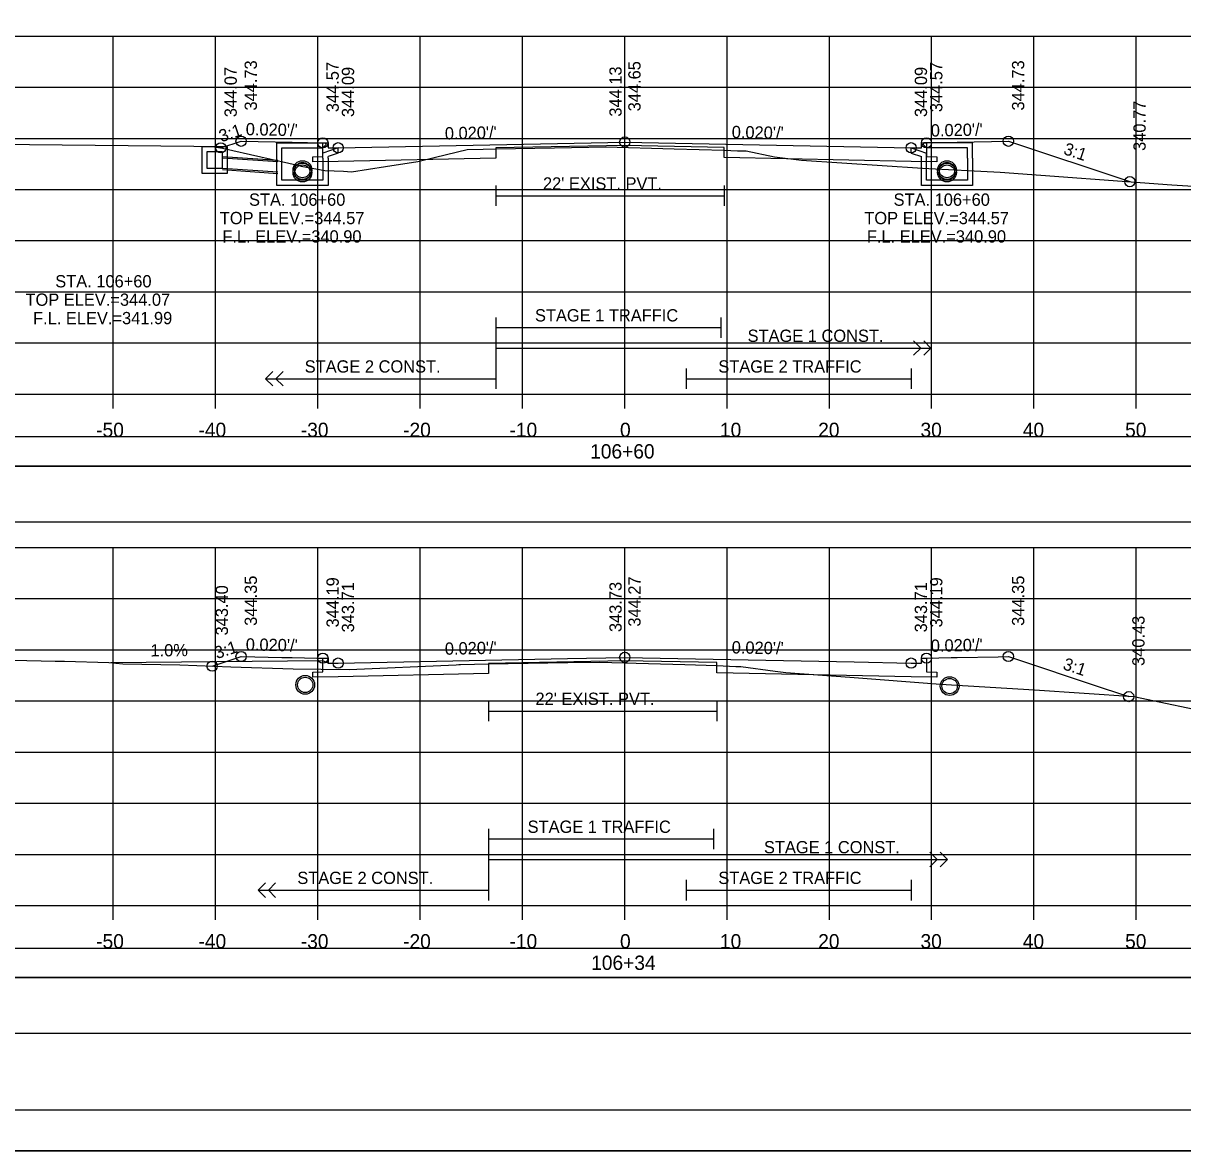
# Model space of a CAD drawing. Extents: x 1368122 to 1710785, y 373130 to 557566.
# Drawn here: x 1368630.1 to 1368743.4, y 374410.4 to 374520.6 of the extents above; entities that cross this region are included whole.
import ezdxf

# ---------------------------------------------------------------- set-up
doc = ezdxf.new("R2010")
doc.units = 0
for name, color, linetype in [('R_Alt Surface', 7, 'Continuous'), ('R_Axis', 7, 'Continuous'), ('R_Axis Annot', 7, 'Continuous'), ('R_Border', 7, 'Continuous'), ('R_Drive', 7, 'Continuous'), ('R_Exist Surface', 7, 'Continuous'), ('R_Fin Surface', 7, 'Continuous'), ('R_Grid', 7, 'Continuous'), ('R_No Plot', 7, 'Continuous'), ('R_Striping', 7, 'Continuous'), ('R_Water', 7, 'Continuous'), ('R_Water Annot', 7, 'Continuous'), ('R_Xsect Elev', 7, 'Continuous'), ('R_Xsect Slope', 7, 'Continuous')]:
    doc.layers.add(name, color=color, linetype=linetype)

msp = doc.modelspace()

# ---------------------------------------------------------------- linework, layer by layer
at = {"layer": 'R_Alt Surface'}
for points in [[(1368718.38, 374508.9), (1368718.38, 374507.56), (1368719.38, 374507.54), (1368719.38, 374507.04), (1368716.88, 374507.09), (1368698.6, 374507.46), (1368698.6, 374508.46), (1368688.88, 374508.65), (1368676.28, 374508.4), (1368676.28, 374507.4), (1368660.88, 374507.09), (1368658.38, 374507.04), (1368658.38, 374507.54), (1368659.38, 374507.56), (1368659.38, 374508.9)], [(1368676.28, 374504.73), (1368676.28, 374502.73)], [(1368698.6, 374504.73), (1368698.6, 374502.73)], [(1368676.28, 374503.73), (1368698.6, 374503.73)], [(1368718.38, 374458.52), (1368718.38, 374457.18), (1368719.38, 374457.16), (1368719.38, 374456.66), (1368716.88, 374456.71), (1368697.87, 374457.09), (1368697.87, 374458.09), (1368688.88, 374458.27), (1368675.55, 374458.01), (1368675.55, 374457.01), (1368660.88, 374456.71), (1368658.38, 374456.66), (1368658.38, 374457.16), (1368659.38, 374457.18), (1368659.38, 374458.52)], [(1368675.55, 374454.35), (1368675.55, 374452.35)], [(1368697.87, 374454.35), (1368697.87, 374452.35)], [(1368675.55, 374453.35), (1368697.87, 374453.35)]]:
    msp.add_lwpolyline(points, dxfattribs=at)
for points in [[(1368539.73, 374477.33), (1368838.03, 374477.33), (1368838.03, 374480.15), (1368539.73, 374480.15)], [(1368539.73, 374471.86), (1368838.03, 374471.86), (1368838.03, 374477.27), (1368539.73, 374477.27)], [(1368539.73, 374427.33), (1368838.03, 374427.33), (1368838.03, 374430.15), (1368539.73, 374430.15)], [(1368539.73, 374421.86), (1368838.03, 374421.86), (1368838.03, 374427.27), (1368539.73, 374427.27)]]:
    msp.add_lwpolyline(points, close=True, dxfattribs=at)
at = {"layer": 'R_Axis'}
for p, q in [((1368538.88, 374484.34), (1368838.88, 374484.34)), ((1368638.88, 374482.94), (1368638.88, 374484.34)), ((1368648.88, 374482.94), (1368648.88, 374484.34)), ((1368658.88, 374482.94), (1368658.88, 374484.34)), ((1368668.88, 374482.94), (1368668.88, 374484.34)), ((1368678.88, 374482.94), (1368678.88, 374484.34)), ((1368688.88, 374482.94), (1368688.88, 374484.34)), ((1368698.88, 374482.94), (1368698.88, 374484.34)), ((1368708.88, 374482.94), (1368708.88, 374484.34)), ((1368718.88, 374482.94), (1368718.88, 374484.34)), ((1368728.88, 374482.94), (1368728.88, 374484.34)), ((1368738.88, 374482.94), (1368738.88, 374484.34)), ((1368538.88, 374434.34), (1368838.88, 374434.34)), ((1368638.88, 374432.94), (1368638.88, 374434.34)), ((1368648.88, 374432.94), (1368648.88, 374434.34)), ((1368658.88, 374432.94), (1368658.88, 374434.34)), ((1368668.88, 374432.94), (1368668.88, 374434.34)), ((1368678.88, 374432.94), (1368678.88, 374434.34)), ((1368688.88, 374432.94), (1368688.88, 374434.34)), ((1368698.88, 374432.94), (1368698.88, 374434.34)), ((1368708.88, 374432.94), (1368708.88, 374434.34)), ((1368718.88, 374432.94), (1368718.88, 374434.34)), ((1368728.88, 374432.94), (1368728.88, 374434.34)), ((1368738.88, 374432.94), (1368738.88, 374434.34))]:
    msp.add_line(p, q, dxfattribs=at)
at = {"layer": 'R_Border'}
msp.add_line((1368847.06, 374414.34), (1368530.88, 374414.34), dxfattribs=at)
at = {"layer": 'R_Drive'}
for p, q in [((1368659.38, 374458.27), (1368638.66, 374458.07)), ((1368659.88, 374458.02), (1368659.38, 374458.27))]:
    msp.add_line(p, q, dxfattribs=at)
at = {"layer": 'R_Exist Surface'}
for points in [[(1368617.79, 374508.86), (1368646.78, 374508.58), (1368648.11, 374508.54), (1368648.37, 374508.54), (1368648.8, 374508.52), (1368649.57, 374508.38), (1368657.07, 374506.69), (1368657.25, 374506.62), (1368659.56, 374506.2), (1368661.38, 374506.13), (1368662.17, 374506.08), (1368665.49, 374506.58), (1368668.66, 374507.07), (1368670.38, 374507.51), (1368673.48, 374508.24), (1368675.03, 374508.28), (1368676.28, 374508.31), (1368682.02, 374508.42), (1368687.02, 374508.52), (1368693.7, 374508.31), (1368698.6, 374508.17), (1368699.92, 374508.13), (1368700.75, 374508.11), (1368703.53, 374507.52), (1368706.17, 374507.2), (1368717.99, 374506.41), (1368725.57, 374506.03), (1368742.37, 374504.81), (1368748.06, 374504.43)], [(1368622.12, 374458.49), (1368633.2, 374458.24), (1368633.75, 374458.22), (1368634.13, 374458.22), (1368638.46, 374458.08), (1368639.84, 374457.97), (1368645.4, 374457.87), (1368650.39, 374457.67), (1368656.47, 374457.47), (1368661.95, 374457.42), (1368672.4, 374457.88), (1368672.66, 374457.89), (1368672.78, 374457.89), (1368672.79, 374457.89), (1368672.82, 374457.89), (1368675.55, 374457.96), (1368683.31, 374458.08), (1368686.44, 374458.14), (1368694.75, 374457.89), (1368697.87, 374457.79), (1368699.75, 374457.72), (1368700.23, 374457.7), (1368703.6, 374457.26), (1368704.62, 374457.12), (1368710.89, 374456.67), (1368719.74, 374455.99), (1368728.94, 374455.43), (1368738.65, 374454.78), (1368747.03, 374453)]]:
    msp.add_lwpolyline(points, dxfattribs=at)
for centre in [(1368657.65, 374455.91), (1368720.64, 374455.79)]:
    msp.add_circle(centre, 0.917, dxfattribs=at)
at = {"layer": 'R_Fin Surface'}
for points in [[(1368649.41, 374508.41), (1368651.38, 374509.06), (1368656.38, 374508.96), (1368659.38, 374508.9), (1368659.88, 374508.9), (1368659.88, 374508.4), (1368660.88, 374508.42), (1368688.88, 374508.98), (1368716.88, 374508.42), (1368717.88, 374508.4), (1368717.88, 374508.9), (1368718.38, 374508.9), (1368721.38, 374508.96), (1368726.38, 374509.06), (1368738.25, 374505.11)], [(1368648.55, 374457.74), (1368650.82, 374458.5), (1368651.38, 374458.68), (1368655.38, 374458.6), (1368656.38, 374458.58), (1368658.78, 374458.53), (1368659.38, 374458.52), (1368659.48, 374458.52), (1368659.88, 374458.52), (1368659.88, 374458.42), (1368659.88, 374458.02), (1368660.68, 374458.04), (1368660.88, 374458.04), (1368683.3, 374458.49), (1368688.88, 374458.6), (1368711.3, 374458.15), (1368716.88, 374458.04), (1368717.08, 374458.04), (1368717.88, 374458.02), (1368717.88, 374458.12), (1368717.88, 374458.52), (1368718.28, 374458.52), (1368718.38, 374458.52), (1368720.78, 374458.57), (1368721.38, 374458.58), (1368725.38, 374458.66), (1368726.38, 374458.68), (1368735.66, 374455.59), (1368738.14, 374454.76)]]:
    msp.add_lwpolyline(points, dxfattribs=at)
at = {"layer": 'R_Grid'}
for p, q in [((1368538.88, 374519.34), (1368838.88, 374519.34)), ((1368638.88, 374484.34), (1368638.88, 374519.34)), ((1368648.88, 374484.34), (1368648.88, 374519.34)), ((1368658.88, 374484.34), (1368658.88, 374519.34)), ((1368668.88, 374484.34), (1368668.88, 374519.34)), ((1368678.88, 374484.34), (1368678.88, 374519.34)), ((1368688.88, 374484.34), (1368688.88, 374519.34)), ((1368698.88, 374484.34), (1368698.88, 374519.34)), ((1368708.88, 374484.34), (1368708.88, 374519.34)), ((1368718.88, 374484.34), (1368718.88, 374519.34)), ((1368728.88, 374484.34), (1368728.88, 374519.34)), ((1368738.88, 374484.34), (1368738.88, 374519.34)), ((1368538.88, 374514.34), (1368838.88, 374514.34)), ((1368538.88, 374509.34), (1368838.88, 374509.34)), ((1368538.88, 374504.34), (1368838.88, 374504.34)), ((1368538.88, 374499.34), (1368838.88, 374499.34)), ((1368538.88, 374494.34), (1368838.88, 374494.34)), ((1368538.88, 374489.34), (1368838.88, 374489.34)), ((1368538.88, 374484.34), (1368838.88, 374484.34)), ((1368538.88, 374469.34), (1368838.88, 374469.34)), ((1368638.88, 374434.34), (1368638.88, 374469.34)), ((1368648.88, 374434.34), (1368648.88, 374469.34)), ((1368658.88, 374434.34), (1368658.88, 374469.34)), ((1368668.88, 374434.34), (1368668.88, 374469.34)), ((1368678.88, 374434.34), (1368678.88, 374469.34)), ((1368688.88, 374434.34), (1368688.88, 374469.34)), ((1368698.88, 374434.34), (1368698.88, 374469.34)), ((1368708.88, 374434.34), (1368708.88, 374469.34)), ((1368718.88, 374434.34), (1368718.88, 374469.34)), ((1368728.88, 374434.34), (1368728.88, 374469.34)), ((1368738.88, 374434.34), (1368738.88, 374469.34)), ((1368538.88, 374464.34), (1368838.88, 374464.34)), ((1368538.88, 374459.34), (1368838.88, 374459.34)), ((1368538.88, 374454.34), (1368838.88, 374454.34)), ((1368538.88, 374449.34), (1368838.88, 374449.34)), ((1368538.88, 374444.34), (1368838.88, 374444.34)), ((1368538.88, 374439.34), (1368838.88, 374439.34)), ((1368538.88, 374434.34), (1368838.88, 374434.34))]:
    msp.add_line(p, q, dxfattribs=at)
at = {"layer": 'R_No Plot'}
for p, q in [((1368649.55, 374507.58), (1368654.99, 374507.22)), ((1368649.55, 374506.28), (1368654.99, 374505.92)), ((1368518.48, 374410.36), (1368851.81, 374410.36))]:
    msp.add_line(p, q, dxfattribs=at)
for points in [[(1368518.47, 374623.69), (1368851.81, 374623.69), (1368851.81, 374410.35), (1368518.47, 374410.35)], [(1368764.8, 374619.8), (1368784.42, 374619.8), (1368784.42, 374609.92), (1368800.53, 374609.92), (1368823.73, 374609.92), (1368823.85, 374581.76), (1368847.06, 374581.76), (1368847.06, 374414.34), (1368530.88, 374414.34), (1368530.88, 374619.8)]]:
    msp.add_lwpolyline(points, close=True, dxfattribs=at)
for centre, radius in [((1368651.38, 374509.06), 0.5), ((1368688.88, 374508.98), 0.5), ((1368726.38, 374509.06), 0.5), ((1368649.41, 374508.41), 0.5), ((1368659.38, 374508.9), 0.5), ((1368660.88, 374508.42), 0.5), ((1368716.88, 374508.42), 0.5), ((1368718.38, 374508.9), 0.5), ((1368657.38, 374506.24), 0.917), ((1368720.38, 374506.24), 0.917), ((1368657.38, 374505.99), 0.917), ((1368720.38, 374505.99), 0.917), ((1368738.25, 374505.11), 0.5), ((1368651.38, 374458.68), 0.5), ((1368659.38, 374458.52), 0.5), ((1368660.88, 374458.04), 0.5), ((1368688.88, 374458.6), 0.5), ((1368716.88, 374458.04), 0.5), ((1368718.38, 374458.52), 0.5), ((1368726.38, 374458.68), 0.5), ((1368648.55, 374457.74), 0.5), ((1368738.14, 374454.76), 0.5)]:
    msp.add_circle(centre, radius, dxfattribs=at)
at = {"layer": 'R_Striping'}
for p, q in [((1368717.81, 374488.84), (1368717.11, 374489.54)), ((1368718.81, 374488.84), (1368718.11, 374489.54)), ((1368717.11, 374488.13), (1368717.81, 374488.84)), ((1368718.11, 374488.13), (1368718.81, 374488.84)), ((1368653.78, 374485.84), (1368654.49, 374486.54)), ((1368653.78, 374485.84), (1368676.28, 374485.84)), ((1368654.49, 374485.13), (1368653.78, 374485.84)), ((1368654.78, 374485.84), (1368655.49, 374486.54)), ((1368655.49, 374485.13), (1368654.78, 374485.84)), ((1368719.42, 374438.84), (1368718.71, 374439.54)), ((1368720.42, 374438.84), (1368719.71, 374439.54)), ((1368718.71, 374438.13), (1368719.42, 374438.84)), ((1368719.71, 374438.13), (1368720.42, 374438.84)), ((1368653.05, 374435.84), (1368653.76, 374436.54)), ((1368653.05, 374435.84), (1368675.55, 374435.84)), ((1368653.76, 374435.13), (1368653.05, 374435.84)), ((1368654.05, 374435.84), (1368654.76, 374436.54)), ((1368654.76, 374435.13), (1368654.05, 374435.84))]:
    msp.add_line(p, q, dxfattribs=at)
for points in [[(1368676.28, 374491.84), (1368676.28, 374484.84)], [(1368698.28, 374491.84), (1368698.28, 374489.84)], [(1368676.28, 374490.84), (1368698.28, 374490.84)], [(1368676.28, 374488.84), (1368718.81, 374488.84)], [(1368694.88, 374486.84), (1368694.88, 374484.84)], [(1368716.88, 374486.84), (1368716.88, 374484.84)], [(1368694.88, 374485.84), (1368716.88, 374485.84)], [(1368675.55, 374441.84), (1368675.55, 374434.84)], [(1368697.55, 374441.84), (1368697.55, 374439.84)], [(1368675.55, 374440.84), (1368697.55, 374440.84)], [(1368675.55, 374438.84), (1368720.42, 374438.84)], [(1368694.88, 374436.84), (1368694.88, 374434.84)], [(1368694.88, 374435.84), (1368716.88, 374435.84)], [(1368716.88, 374436.84), (1368716.88, 374434.84)]]:
    msp.add_lwpolyline(points, dxfattribs=at)
at = {"layer": 'R_Water'}
for p, q in [((1368654.88, 374508.9), (1368659.63, 374508.9)), ((1368654.88, 374507.4), (1368654.88, 374508.9)), ((1368655.38, 374507.4), (1368655.38, 374508.4)), ((1368655.38, 374508.4), (1368659.38, 374508.4)), ((1368659.71, 374508.74), (1368659.38, 374508.4)), ((1368660.88, 374508.42), (1368659.38, 374507.9)), ((1368659.71, 374508.74), (1368659.63, 374508.9)), ((1368716.88, 374508.42), (1368718.38, 374507.9)), ((1368718.05, 374508.74), (1368718.13, 374508.9)), ((1368718.05, 374508.74), (1368718.38, 374508.4)), ((1368722.88, 374508.9), (1368718.13, 374508.9)), ((1368722.38, 374508.4), (1368718.38, 374508.4)), ((1368722.38, 374507.4), (1368722.38, 374508.4)), ((1368722.88, 374507.4), (1368722.88, 374508.9)), ((1368649.55, 374507.43), (1368654.99, 374507.07)), ((1368659.38, 374507.4), (1368659.38, 374507.9)), ((1368660.88, 374507.89), (1368659.88, 374507.55)), ((1368659.88, 374507.4), (1368659.88, 374507.55)), ((1368716.88, 374507.89), (1368717.88, 374507.55)), ((1368717.88, 374507.4), (1368717.88, 374507.55)), ((1368718.38, 374507.4), (1368718.38, 374507.9)), ((1368649.55, 374506.43), (1368654.99, 374506.07))]:
    msp.add_line(p, q, dxfattribs=at)
for points in [[(1368648.8, 374508.52), (1368647.55, 374508.52), (1368647.55, 374505.93), (1368648.8, 374505.93), (1368650.05, 374505.93), (1368650.05, 374508.52)], [(1368648.8, 374508.02), (1368648.05, 374508.02), (1368648.05, 374506.43), (1368648.8, 374506.43), (1368649.55, 374506.43), (1368649.55, 374508.02)]]:
    msp.add_lwpolyline(points, close=True, dxfattribs=at)
for points in [[(1368660.88, 374507.89), (1368660.88, 374508.42)], [(1368716.88, 374507.89), (1368716.88, 374508.42)], [(1368659.88, 374507.4), (1368659.88, 374504.74), (1368657.38, 374504.74), (1368654.88, 374504.74), (1368654.88, 374507.4)], [(1368659.38, 374507.4), (1368659.38, 374505.24), (1368657.38, 374505.24), (1368655.38, 374505.24), (1368655.38, 374507.4)], [(1368722.88, 374507.4), (1368722.88, 374504.74), (1368720.38, 374504.74), (1368717.88, 374504.74), (1368717.88, 374507.4)], [(1368722.38, 374507.4), (1368722.38, 374505.24), (1368720.38, 374505.24), (1368718.38, 374505.24), (1368718.38, 374507.4)]]:
    msp.add_lwpolyline(points, dxfattribs=at)
for centre in [(1368657.38, 374506.24), (1368657.38, 374505.99), (1368720.38, 374506.24), (1368720.38, 374505.99), (1368657.65, 374455.91), (1368720.64, 374455.79)]:
    msp.add_circle(centre, 0.75, dxfattribs=at)
at = {"layer": 'R_Xsect Elev'}
for p, q in [((1368688.88, 374508.46), (1368688.88, 374518.46)), ((1368688.88, 374458.07), (1368688.88, 374468.07))]:
    msp.add_line(p, q, dxfattribs=at)

# ---------------------------------------------------------------- texts
at = {"layer": 'R_Axis Annot'}
for s, p in [('-50', (1368637.22, 374480.14)), ('-40', (1368647.22, 374480.14)), ('-30', (1368657.22, 374480.14)), ('-20', (1368667.22, 374480.14)), ('-10', (1368677.62, 374480.14)), ('0', (1368688.42, 374480.14)), ('10', (1368698.19, 374480.14)), ('20', (1368707.79, 374480.14)), ('30', (1368717.79, 374480.14)), ('40', (1368727.79, 374480.14)), ('50', (1368737.79, 374480.14)), ('106+60', (1368685.5, 374478.04)), ('-50', (1368637.22, 374430.14)), ('-40', (1368647.22, 374430.14)), ('-30', (1368657.22, 374430.14)), ('-20', (1368667.22, 374430.14)), ('-10', (1368677.62, 374430.14)), ('0', (1368688.42, 374430.14)), ('10', (1368698.19, 374430.14)), ('20', (1368707.79, 374430.14)), ('30', (1368717.79, 374430.14)), ('40', (1368727.79, 374430.14)), ('50', (1368737.79, 374430.14)), ('106+34', (1368685.6, 374428.04))]:
    msp.add_text(s, height=1.4, dxfattribs=at).set_placement(p)
at = {"layer": 'R_Striping'}
for s, p in [('STAGE 1 TRAFFIC', (1368680.11, 374491.44)), ('STAGE 1 CONST.', (1368700.89, 374489.44)), ('STAGE 2 CONST.', (1368657.6, 374486.44)), ('STAGE 2 TRAFFIC', (1368698.03, 374486.44)), ('STAGE 1 TRAFFIC', (1368679.39, 374441.44)), ('STAGE 1 CONST.', (1368702.49, 374439.44)), ('STAGE 2 CONST.', (1368656.88, 374436.44)), ('STAGE 2 TRAFFIC', (1368698.03, 374436.44))]:
    msp.add_text(s, height=1.2, dxfattribs=at).set_placement(p)
at = {"layer": 'R_Water'}
for p in [(1368680.89, 374504.33), (1368680.16, 374453.95)]:
    msp.add_text("22' EXIST. PVT.", height=1.2, dxfattribs=at).set_placement(p)
at = {"layer": 'R_Water Annot'}
for s, p in [('STA. 106+60', (1368652.16, 374502.75)), ('STA. 106+60', (1368715.16, 374502.75)), ('TOP ELEV.=344.57', (1368649.3, 374500.95)), ('TOP ELEV.=344.57', (1368712.3, 374500.95)), ('F.L. ELEV.=340.90', (1368649.55, 374499.15)), ('F.L. ELEV.=340.90', (1368712.55, 374499.15)), ('STA. 106+60', (1368633.22, 374494.77)), ('TOP ELEV.=344.07', (1368630.31, 374492.97)), ('F.L. ELEV.=341.99', (1368631.05, 374491.17))]:
    msp.add_text(s, height=1.2, dxfattribs=at).set_placement(p)
at = {"layer": 'R_Xsect Elev'}
for s, rotation, p in [('344.07', 90, (1368650.96, 374511.41)), ('344.73', 90, (1368652.93, 374512.06)), ('344.57', 90, (1368660.93, 374511.9)), ('344.09', 90, (1368662.43, 374511.42)), ('344.13', 90, (1368688.58, 374511.46)), ('344.65', 90, (1368690.43, 374511.98)), ('344.09', 90, (1368718.43, 374511.42)), ('344.57', 90, (1368719.93, 374511.9)), ('344.73', 90, (1368727.93, 374512.06)), ('340.77', 90, (1368739.8, 374508.11)), ('344.35', 90, (1368652.93, 374461.68)), ('344.19', 90, (1368660.93, 374461.52)), ('344.27', 90, (1368690.43, 374461.6)), ('344.19', 90, (1368719.93, 374461.52)), ('344.35', 90, (1368727.93, 374461.68)), ('343.40', 90, (1368650.1, 374460.74)), ('343.71', 90, (1368662.43, 374461.04)), ('343.73', 90, (1368688.58, 374461.07)), ('343.71', 90, (1368718.43, 374461.04)), ('340.43', 90, (1368739.69, 374457.76)), ('1.0%', 0.5729, (1368642.53, 374458.68))]:
    msp.add_text(s, height=1.2, rotation=rotation, dxfattribs=at).set_placement(p)
at = {"layer": 'R_Xsect Slope'}
for s, rotation, p in [('3:1', 18.4349, (1368649.45, 374508.95)), ("0.020'/'", 358.8542, (1368651.83, 374509.65)), ("0.020'/'", 1.1458, (1368671.31, 374509.23)), ("0.020'/'", 358.8542, (1368699.33, 374509.37)), ("0.020'/'", 1.1458, (1368718.81, 374509.51)), ('3:1', 341.5651, (1368731.69, 374507.82)), ('3:1', 18.4349, (1368649.02, 374458.42)), ("0.020'/'", 358.8542, (1368651.83, 374459.27)), ("0.020'/'", 1.1458, (1368671.31, 374458.85)), ("0.020'/'", 358.8542, (1368699.33, 374458.99)), ("0.020'/'", 1.1458, (1368718.81, 374459.13)), ('3:1', 341.5651, (1368731.63, 374457.46))]:
    msp.add_text(s, height=1.2, rotation=rotation, dxfattribs=at).set_placement(p)

doc.saveas('drawing.dxf')
